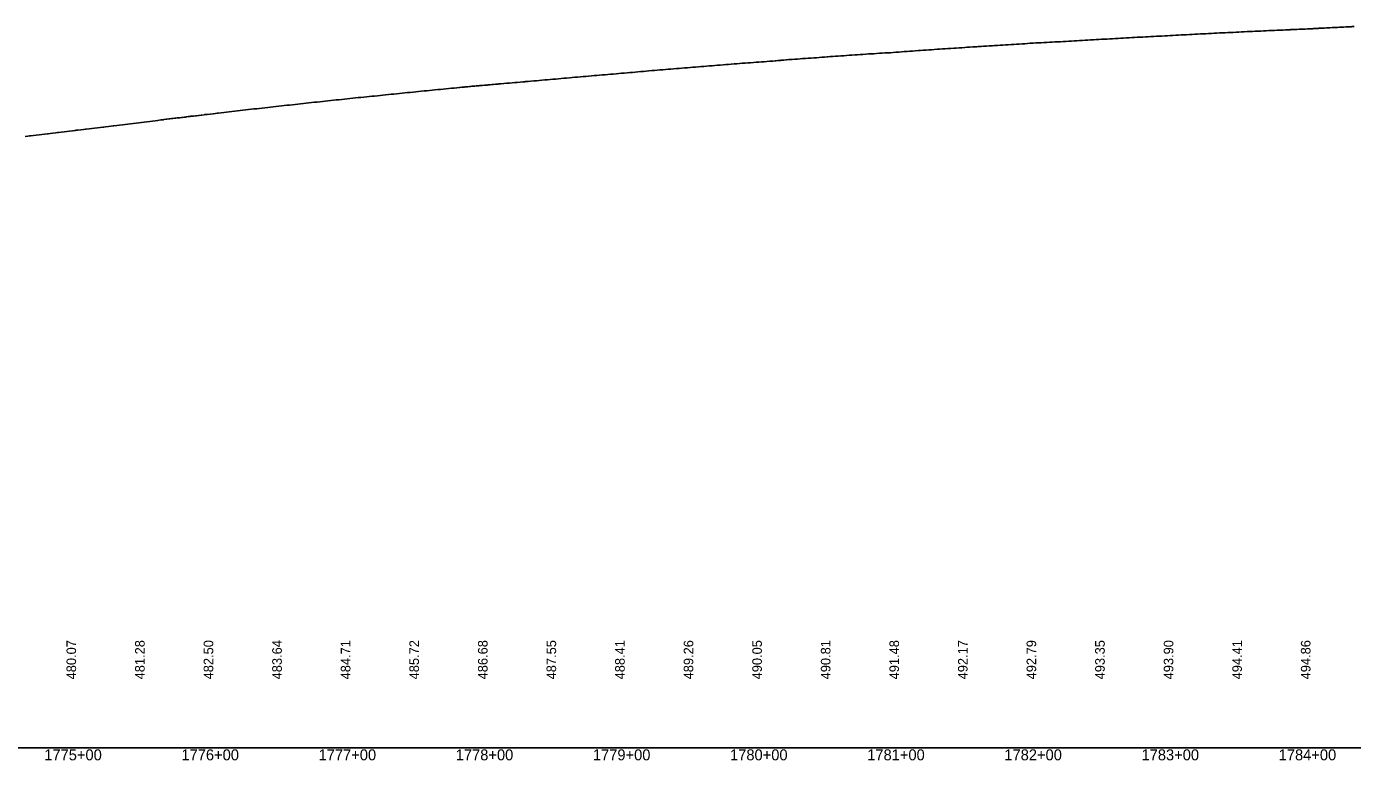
# Model space of a CAD drawing. Extents: x 2017200 to 2047700, y 854850 to 893350.
# Drawn here: x 2032463 to 2033430, y 856091 to 856626 of the extents above; entities that cross this region are included whole.
import ezdxf

# ---------------------------------------------------------------- set-up
doc = ezdxf.new("R2010")
doc.units = 0
for name, color, linetype in [('RD_DDB_Profile_EX', 7, 'Continuous'), ('RD_DDB_StaTX', 7, 'Continuous'), ('RD_DDB_StripGrade', 7, 'Continuous'), ('RD_GPK_Profile_Cell', 7, 'Continuous')]:
    doc.layers.add(name, color=color, linetype=linetype)

msp = doc.modelspace()

# ---------------------------------------------------------------- linework, layer by layer
at = {"layer": 'RD_DDB_Profile_EX'}
for points in [[(2032586.68, 856560.91), (2032588.15, 856561.08), (2032588.68, 856561.15), (2032590.24, 856561.32), (2032590.68, 856561.36), (2032592.31, 856561.59), (2032592.68, 856561.65), (2032594.68, 856561.87), (2032596.68, 856562.12), (2032598.82, 856562.36), (2032600.68, 856562.57), (2032601.83, 856562.71), (2032602.68, 856562.8), (2032604.69, 856563.04), (2032606.69, 856563.29), (2032608.68, 856563.52), (2032610.67, 856563.75), (2032612.65, 856563.99), (2032614.72, 856564.21), (2032616.7, 856564.44), (2032618.68, 856564.65), (2032620.66, 856564.89), (2032622.64, 856565.11), (2032624.72, 856565.37), (2032626.7, 856565.57), (2032628.68, 856565.8), (2032630.66, 856566.02), (2032632.65, 856566.26), (2032634.71, 856566.48), (2032636.7, 856566.72), (2032638.68, 856566.96), (2032640.66, 856567.16), (2032642.64, 856567.41), (2032644.71, 856567.61), (2032646.7, 856567.84), (2032648.68, 856568.03), (2032650.66, 856568.26), (2032652.64, 856568.47), (2032654.71, 856568.68), (2032656.7, 856568.89), (2032658.68, 856569.1), (2032660.66, 856569.33), (2032662.64, 856569.53), (2032664.72, 856569.77), (2032666.7, 856570), (2032668.68, 856570.21), (2032670.66, 856570.43), (2032672.64, 856570.65), (2032674.71, 856570.88), (2032676.69, 856571.1), (2032678.67, 856571.31), (2032680.66, 856571.52), (2032682.65, 856571.74), (2032684.7, 856571.95), (2032686.68, 856572.17), (2032688.67, 856572.36), (2032690.66, 856572.58), (2032692.66, 856572.77), (2032694.68, 856572.98), (2032696.68, 856573.19), (2032698.67, 856573.41), (2032700.67, 856573.62), (2032702.66, 856573.81), (2032704.68, 856574.04), (2032706.68, 856574.21), (2032708.67, 856574.42), (2032710.66, 856574.62), (2032712.65, 856574.82), (2032714.69, 856575.05), (2032716.68, 856575.22), (2032718.67, 856575.46), (2032720.66, 856575.65), (2032722.65, 856575.88), (2032724.69, 856576.11), (2032726.68, 856576.31), (2032728.67, 856576.54), (2032730.66, 856576.71), (2032732.65, 856576.93), (2032734.69, 856577.13), (2032736.68, 856577.32), (2032738.67, 856577.52), (2032740.66, 856577.7), (2032742.66, 856577.9), (2032744.68, 856578.09), (2032746.68, 856578.29), (2032748.67, 856578.49), (2032750.66, 856578.69), (2032752.66, 856578.9), (2032754.67, 856579.11), (2032756.74, 856579.34), (2032758.73, 856579.52), (2032760.67, 856579.72), (2032762.67, 856579.9), (2032764.69, 856580.11), (2032766.67, 856580.31), (2032768.67, 856580.49), (2032770.66, 856580.69), (2032772.63, 856580.88), (2032774.67, 856581.07), (2032776.67, 856581.28), (2032778.26, 856581.42), (2032778.67, 856581.45), (2032780.12, 856581.59), (2032780.67, 856581.65), (2032782, 856581.77), (2032782.67, 856581.82), (2032783.88, 856581.94), (2032784.67, 856582.02), (2032785.76, 856582.12), (2032786.67, 856582.21), (2032787.64, 856582.31), (2032788.67, 856582.39), (2032789.82, 856582.5), (2032790.67, 856582.58), (2032791.45, 856582.65), (2032792.67, 856582.74), (2032793.42, 856582.81), (2032794.67, 856582.93), (2032795.4, 856582.99), (2032796.67, 856583.08), (2032797.37, 856583.14), (2032798.67, 856583.26), (2032799.34, 856583.32), (2032800.67, 856583.45), (2032802.08, 856583.57), (2032802.67, 856583.62), (2032803.21, 856583.67), (2032804.67, 856583.81), (2032805.14, 856583.85), (2032806.67, 856583.98), (2032807.06, 856584.01), (2032808.67, 856584.16), (2032810.92, 856584.37), (2032812.91, 856584.54), (2032814.89, 856584.7), (2032816.87, 856584.89), (2032818.85, 856585.05), (2032820.67, 856585.19), (2032822.77, 856585.37), (2032824.71, 856585.55), (2032826.27, 856585.67), (2032826.67, 856585.71), (2032828.67, 856585.89), (2032830.67, 856586.06), (2032832.67, 856586.22), (2032834.67, 856586.39), (2032836.67, 856586.56), (2032838.67, 856586.74), (2032840.67, 856586.92), (2032842.67, 856587.1), (2032844.67, 856587.27), (2032846.67, 856587.47), (2032848.67, 856587.64), (2032850.67, 856587.81), (2032852.67, 856587.97), (2032854.67, 856588.14), (2032856.67, 856588.32), (2032858.67, 856588.53), (2032860.67, 856588.7), (2032862.67, 856588.89), (2032864.67, 856589.06), (2032866.67, 856589.21), (2032868.67, 856589.37), (2032870.67, 856589.56), (2032872.67, 856589.71), (2032874.67, 856589.89), (2032876.67, 856590.08), (2032878.67, 856590.26), (2032880.67, 856590.41), (2032882.67, 856590.61), (2032884.67, 856590.76), (2032886.67, 856590.94), (2032888.67, 856591.12), (2032890.67, 856591.29), (2032892.67, 856591.46), (2032894.67, 856591.61), (2032896.67, 856591.78), (2032898.67, 856591.94), (2032900.67, 856592.11), (2032902.67, 856592.31), (2032904.67, 856592.47), (2032906.67, 856592.64), (2032908.67, 856592.79), (2032910.67, 856593.01), (2032912.67, 856593.21), (2032914.67, 856593.4), (2032916.67, 856593.56), (2032918.67, 856593.77), (2032920.67, 856593.9), (2032922.67, 856594.06), (2032924.67, 856594.22), (2032926.67, 856594.38), (2032928.68, 856594.55), (2032930.68, 856594.72), (2032932.68, 856594.89), (2032934.68, 856595.04), (2032936.68, 856595.19), (2032938.68, 856595.37), (2032940.68, 856595.55), (2032942.68, 856595.73), (2032944.68, 856595.9), (2032946.68, 856596.07), (2032948.68, 856596.21), (2032950.68, 856596.36), (2032952.68, 856596.54), (2032954.68, 856596.67), (2032956.68, 856596.85), (2032958.68, 856597.01), (2032960.68, 856597.19), (2032962.68, 856597.35), (2032964.68, 856597.5), (2032966.68, 856597.67), (2032968.68, 856597.82), (2032970.68, 856598), (2032972.68, 856598.16), (2032974.68, 856598.33), (2032976.68, 856598.49), (2032978.68, 856598.65), (2032980.68, 856598.81), (2032982.68, 856598.95), (2032984.67, 856599.11), (2032985.2, 856599.14), (2032986.74, 856599.24), (2032988.83, 856599.39), (2032990.67, 856599.53), (2032992.82, 856599.71), (2032994.75, 856599.85), (2032996.85, 856600), (2032998.68, 856600.13), (2033000.68, 856600.28), (2033002.59, 856600.42), (2033004.82, 856600.58), (2033006.95, 856600.76), (2033008.68, 856600.91), (2033009.09, 856600.94), (2033010.68, 856601.07), (2033012.21, 856601.21), (2033012.68, 856601.25), (2033013.12, 856601.3), (2033014.68, 856601.45), (2033015.08, 856601.48), (2033016.68, 856601.6), (2033017.04, 856601.63), (2033018.68, 856601.77), (2033019, 856601.8), (2033020.97, 856601.93), (2033022.94, 856602.06), (2033024.91, 856602.19), (2033026.89, 856602.36), (2033028.68, 856602.52), (2033030.84, 856602.69), (2033032.86, 856602.82), (2033034.89, 856602.93), (2033036.91, 856603.05), (2033038.93, 856603.19), (2033040.68, 856603.32), (2033042.68, 856603.46), (2033044.77, 856603.64), (2033046.69, 856603.79), (2033047.08, 856603.82), (2033048.68, 856603.94), (2033050.68, 856604.1), (2033052.68, 856604.24), (2033054.68, 856604.36), (2033056.68, 856604.5), (2033058.68, 856604.65), (2033060.68, 856604.78), (2033062.68, 856604.93), (2033064.68, 856605.05), (2033066.68, 856605.17), (2033068.68, 856605.32), (2033070.68, 856605.45), (2033072.68, 856605.61), (2033074.68, 856605.73), (2033076.68, 856605.88), (2033078.68, 856605.96), (2033080.68, 856606.1), (2033082.68, 856606.24), (2033084.68, 856606.39), (2033086.68, 856606.54), (2033088.68, 856606.66), (2033090.68, 856606.65), (2033092.68, 856606.68), (2033094.68, 856607.01), (2033096.68, 856607.13), (2033097.12, 856607.17), (2033098.74, 856607.31), (2033100.68, 856607.46), (2033102.81, 856607.61), (2033104.82, 856607.77), (2033106.82, 856607.9), (2033108.82, 856608.05), (2033110.68, 856608.16), (2033112.99, 856608.35), (2033114.68, 856608.47), (2033116.69, 856608.61), (2033118.69, 856608.75), (2033120.69, 856608.89), (2033122.69, 856609.02), (2033124.69, 856609.16), (2033126.69, 856609.31), (2033128.69, 856609.43), (2033130.69, 856609.58), (2033132.69, 856609.69), (2033134.68, 856609.83), (2033135.11, 856609.86), (2033136.81, 856609.96), (2033138.96, 856610.08), (2033140.68, 856610.19), (2033142.93, 856610.33), (2033144.81, 856610.48), (2033146.87, 856610.63), (2033148.69, 856610.78), (2033150.69, 856610.9), (2033152.69, 856611.03), (2033154.69, 856611.11), (2033155.62, 856611.17), (2033156.74, 856611.25), (2033158.83, 856611.37), (2033160.69, 856611.49), (2033162.83, 856611.61), (2033164.77, 856611.72), (2033166.7, 856611.79), (2033167.12, 856611.83), (2033168.69, 856611.96), (2033170.69, 856612.09), (2033172.69, 856612.23), (2033174.69, 856612.37), (2033176.69, 856612.49), (2033178.69, 856612.62), (2033180.69, 856612.72), (2033182.69, 856612.87), (2033184.69, 856612.96), (2033186.69, 856613.12), (2033188.69, 856613.23), (2033190.69, 856613.39), (2033192.69, 856613.5), (2033194.69, 856613.65), (2033196.69, 856613.74), (2033198.69, 856613.89), (2033200.69, 856613.99), (2033202.69, 856614.13), (2033204.69, 856614.24), (2033206.69, 856614.37), (2033208.69, 856614.47), (2033210.69, 856614.58), (2033212.69, 856614.68), (2033214.69, 856614.77), (2033216.7, 856614.86), (2033218.7, 856614.95), (2033220.7, 856615.07), (2033222.7, 856615.18), (2033224.7, 856615.29), (2033226.7, 856615.39), (2033228.7, 856615.5), (2033230.7, 856615.62), (2033232.7, 856615.75), (2033234.7, 856615.87), (2033236.7, 856615.99), (2033238.7, 856616.11), (2033240.7, 856616.23), (2033242.7, 856616.35), (2033244.7, 856616.47), (2033246.7, 856616.57), (2033248.7, 856616.7), (2033250.7, 856616.79), (2033252.7, 856616.93), (2033254.7, 856617.04), (2033256.7, 856617.15), (2033258.7, 856617.26), (2033260.7, 856617.39), (2033262.7, 856617.49), (2033264.7, 856617.62), (2033266.7, 856617.71), (2033268.7, 856617.85), (2033270.7, 856617.92), (2033272.7, 856618.05), (2033274.7, 856618.14), (2033276.7, 856618.26), (2033278.7, 856618.35), (2033280.71, 856618.48), (2033282.71, 856618.56), (2033284.71, 856618.71), (2033286.71, 856618.78), (2033288.71, 856618.9), (2033290.71, 856618.98), (2033292.71, 856619.11), (2033294.71, 856619.19), (2033296.71, 856619.32), (2033298.71, 856619.4), (2033300.71, 856619.54), (2033302.71, 856619.62), (2033304.71, 856619.75), (2033306.71, 856619.81), (2033308.71, 856619.93), (2033310.71, 856620.02), (2033312.71, 856620.14), (2033314.71, 856620.26), (2033316.71, 856620.39), (2033318.71, 856620.47), (2033320.72, 856620.61), (2033322.72, 856620.67), (2033324.72, 856620.79), (2033326.72, 856620.87), (2033328.72, 856621), (2033330.72, 856621.08), (2033332.72, 856621.22), (2033334.72, 856621.28), (2033336.72, 856621.39), (2033338.72, 856621.44), (2033340.72, 856621.54), (2033342.72, 856621.64), (2033344.72, 856621.75), (2033346.72, 856621.84), (2033348.72, 856621.98), (2033350.72, 856622.06), (2033352.72, 856622.16), (2033354.72, 856622.24), (2033356.72, 856622.34), (2033358.72, 856622.44), (2033360.72, 856622.54), (2033362.71, 856622.62), (2033364.71, 856622.71), (2033366.71, 856622.82), (2033368.71, 856622.89), (2033370.71, 856622.99), (2033372.71, 856623.07), (2033374.63, 856623.18), (2033376.9, 856623.24), (2033378.71, 856623.35), (2033379.08, 856623.36), (2033380.71, 856623.42), (2033382.22, 856623.51), (2033382.71, 856623.53), (2033384.24, 856623.59), (2033384.71, 856623.61), (2033385.18, 856623.63), (2033386.71, 856623.69), (2033387.16, 856623.72), (2033388.71, 856623.78), (2033389.14, 856623.8), (2033390.71, 856623.88), (2033391.12, 856623.89), (2033392.71, 856623.95), (2033393.11, 856623.97), (2033394.71, 856624.05), (2033395.09, 856624.07), (2033396.71, 856624.14), (2033397.08, 856624.16), (2033398.71, 856624.24), (2033400.37, 856624.32), (2033400.71, 856624.33), (2033401.05, 856624.35), (2033402.71, 856624.46), (2033403.08, 856624.48), (2033404.71, 856624.57), (2033405.1, 856624.59), (2033406.71, 856624.73), (2033407.13, 856624.74), (2033408.71, 856624.79), (2033409.15, 856624.82), (2033410.71, 856624.9), (2033411.17, 856624.92), (2033412.72, 856624.99), (2033413.19, 856625.02), (2033414.72, 856625.09), (2033415.21, 856625.12), (2033416.72, 856625.18), (2033418.19, 856625.27), (2033418.72, 856625.3), (2033420.18, 856625.38), (2033420.72, 856625.4), (2033421.27, 856625.43), (2033422.72, 856625.49), (2033423.31, 856625.51), (2033424.72, 856625.57), (2033425.35, 856625.61), (2033426.72, 856625.68), (2033427.39, 856625.71), (2033428.72, 856625.79), (2033429.42, 856625.83), (2033430.72, 856625.9)], [(2032461.9, 856545.81), (2032463.92, 856546.07), (2032465.12, 856546.19), (2032465.94, 856546.28), (2032467.97, 856546.52), (2032469.99, 856546.74), (2032472.01, 856547), (2032474.04, 856547.23), (2032476.06, 856547.46), (2032478.08, 856547.71), (2032478.66, 856547.78), (2032480.11, 856547.95), (2032482.13, 856548.2), (2032484.15, 856548.45), (2032485.43, 856548.62), (2032486.17, 856548.73), (2032488.2, 856548.97), (2032490.22, 856549.21), (2032492.24, 856549.45), (2032494.27, 856549.69), (2032496.29, 856549.94), (2032498.31, 856550.19), (2032498.97, 856550.26), (2032500.33, 856550.41), (2032502.36, 856550.67), (2032504.38, 856550.9), (2032505.74, 856551.07), (2032506.4, 856551.15), (2032508.42, 856551.37), (2032510.45, 856551.63), (2032512.51, 856551.85), (2032514.49, 856552.08), (2032516.52, 856552.32), (2032518.54, 856552.56), (2032519.28, 856552.64), (2032520.56, 856552.8), (2032522.58, 856553.05), (2032524.61, 856553.31), (2032526.04, 856553.49), (2032526.63, 856553.57), (2032528.65, 856553.84), (2032530.67, 856554.07), (2032532.81, 856554.35), (2032534.7, 856554.55), (2032536.7, 856554.81), (2032538.69, 856555.04), (2032540.69, 856555.28), (2032542.69, 856555.53), (2032544.69, 856555.75), (2032546.69, 856556.01), (2032548.69, 856556.23), (2032550.69, 856556.49), (2032552.69, 856556.72), (2032554.69, 856556.98), (2032556.68, 856557.25), (2032558.35, 856557.43), (2032558.68, 856557.47), (2032560.83, 856557.77), (2032562.68, 856557.98), (2032563.03, 856558.02), (2032564.68, 856558.25), (2032565.22, 856558.32), (2032566.68, 856558.49), (2032567.42, 856558.59), (2032568.68, 856558.76), (2032569.6, 856558.86), (2032570.68, 856558.98), (2032571.66, 856559.09), (2032572.68, 856559.22), (2032573.73, 856559.34), (2032574.68, 856559.46), (2032575.76, 856559.59), (2032576.68, 856559.69), (2032577.78, 856559.83), (2032578.68, 856559.94), (2032579.55, 856560.05), (2032580.68, 856560.2), (2032581.89, 856560.34), (2032582.68, 856560.44), (2032583.97, 856560.59), (2032584.68, 856560.66), (2032586.06, 856560.83), (2032586.68, 856560.91)]]:
    msp.add_lwpolyline(points, dxfattribs=at)
at = {"layer": 'RD_GPK_Profile_Cell'}
msp.add_line((2020500, 856100), (2047700, 856100), dxfattribs=at)

# ---------------------------------------------------------------- texts
at = {"layer": 'RD_DDB_StaTX'}
for s, p in [('1775+00', (2032475.8, 856091)), ('1776+00', (2032575.8, 856091)), ('1777+00', (2032675.8, 856091)), ('1778+00', (2032775.8, 856091)), ('1779+00', (2032875.8, 856091)), ('1780+00', (2032975.8, 856091)), ('1781+00', (2033075.8, 856091)), ('1782+00', (2033175.8, 856091)), ('1783+00', (2033275.8, 856091)), ('1784+00', (2033375.8, 856091))]:
    msp.add_text(s, height=8, dxfattribs=at).set_placement(p)
at = {"layer": 'RD_DDB_StripGrade'}
for s, p in [('480.07', (2032499, 856150)), ('481.28', (2032549, 856150)), ('482.50', (2032599, 856150)), ('483.64', (2032649, 856150)), ('484.71', (2032699, 856150)), ('485.72', (2032749, 856150)), ('486.68', (2032799, 856150)), ('487.55', (2032849, 856150)), ('488.41', (2032899, 856150)), ('489.26', (2032949, 856150)), ('490.05', (2032999, 856150)), ('490.81', (2033049, 856150)), ('491.48', (2033099, 856150)), ('492.17', (2033149, 856150)), ('492.79', (2033199, 856150)), ('493.35', (2033249, 856150)), ('493.90', (2033299, 856150)), ('494.41', (2033349, 856150)), ('494.86', (2033399, 856150))]:
    msp.add_text(s, height=7, rotation=90, dxfattribs=at).set_placement(p)

doc.saveas('drawing.dxf')
